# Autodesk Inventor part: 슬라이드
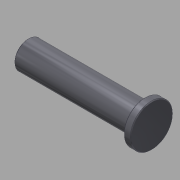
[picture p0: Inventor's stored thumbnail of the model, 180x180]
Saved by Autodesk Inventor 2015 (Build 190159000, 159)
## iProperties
Created: 2015-10
Part Number: 슬라이드
Document SubType Name: Modeling
Designer: mdu
Density: 7.86 g/cm^3
Material: 강철, 연강
Appearance: 강철 - 광택
Mass: 1603.27 g
Surface Area: 269.019 cm^2
Volume: 203.978 cm^3
Author: mdu
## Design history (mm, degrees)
sketch "스케치1"
  geometry: L1 (-75, 162)-(-75, 58) reference; L2 (-148, 110)-(22, 110); L3 (-148, 110)-(-148, 129); L4 (-148, 129)-(12, 129); L5 (12, 129)-(12, 139); L6 (12, 139)-(22, 139); L7 (22, 139)-(22, 110); 2 further points
  constraints: 12 end point, 3 parallel, 3 perpendicular, 1 midpoint, 1 point on line
  dimensions: "d0" = 58 diameter of L6 L2; "d1" = 38 diameter of L4 L2; "d2" = 10 distance of L5.end L6.end; "d3" = 170 distance of L2.start L2.end; "d4" = 73 distance between parallel lines of L3 L1
revolve "회전1" sketch "스케치1" stored, may be unused: angle "d5" = 90 deg
hole "구멍1" diameter "d11" = 13.376; stored, may be unused: countersink angle "d15" = 90 deg, drill point angle "d17" = 118 deg; dims "d9" = 10, "d10" = 10, "d12" = 22, "d13" = 4, "d14" = 2, "d16" = 25
chamfer "모따기1" distance "d6" = 1; stored, may be unused: second distance "d7" = 2, angle "d8" = 45 deg
node "솔리드1"
node "참조1"
